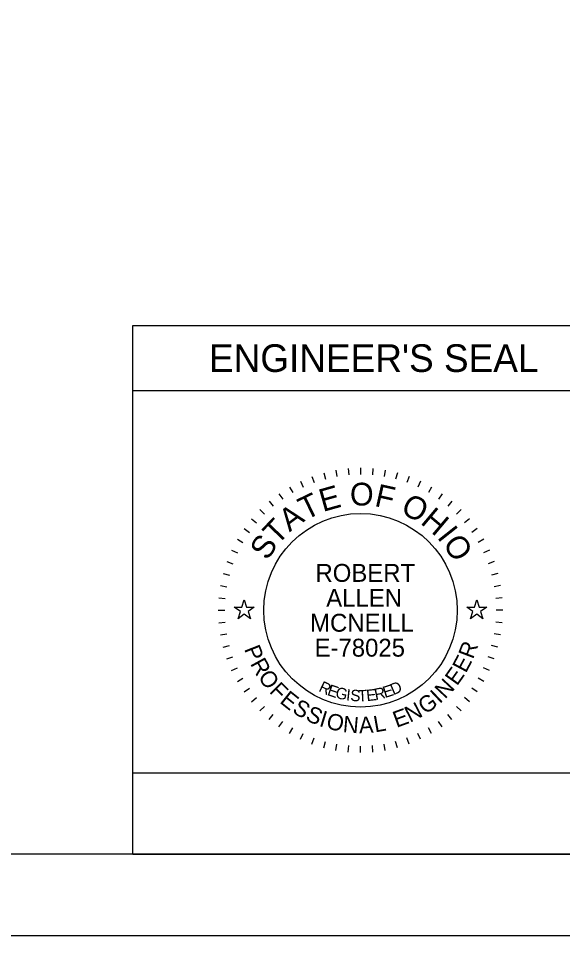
# Model space of a CAD drawing. Extents: x 0 to 34, y 0 to 22.
# Drawn here: x 6.64 to 9.99, y 0 to 5.64 of the extents above; entities that cross this region are included whole.
import ezdxf

# ---------------------------------------------------------------- set-up
doc = ezdxf.new("R2010")
doc.units = 0
for name, color, linetype in [('Default', 7, 'Continuous'), ('SH_Border', 7, 'Continuous'), ('SH_Cut_Line', 7, 'Continuous'), ('SH_Data', 7, 'Continuous')]:
    doc.layers.add(name, color=color, linetype=linetype)

msp = doc.modelspace()

# ---------------------------------------------------------------- linework, layer by layer
at = {"layer": 'Default'}
for points in [[(7.9736, 2.02), (8.0205, 2.02), (8.035, 2.0645), (8.0495, 2.02), (8.0964, 2.02), (8.0585, 1.9924), (8.073, 1.9478), (8.035, 1.9754), (7.997, 1.9478), (8.0115, 1.9924)], [(9.4036, 2.02), (9.4505, 2.02), (9.465, 2.0645), (9.4795, 2.02), (9.5264, 2.02), (9.4885, 1.9924), (9.503, 1.9478), (9.465, 1.9754), (9.427, 1.9478), (9.4415, 1.9924)]]:
    msp.add_lwpolyline(points, close=True, dxfattribs=at)
at = {"layer": 'SH_Border'}
msp.add_lwpolyline([(1.5, 21.5), (33.5, 21.5), (33.5, 0.5), (1.5, 0.5)], close=True, dxfattribs=at)
at = {"layer": 'SH_Cut_Line'}
msp.add_lwpolyline([(0, 0), (34, 0), (34, 22), (0, 22)], close=True, dxfattribs=at)
at = {"layer": 'SH_Data'}
for p, q in [((7.35, 0.5), (7.35, 3.75)), ((7.35, 3.75), (10.15, 3.75)), ((7.35, 3.35), (10.15, 3.35)), ((8.4507, 2.8222), (8.4644, 2.7846)), ((8.5235, 2.8452), (8.5339, 2.8065)), ((8.5981, 2.8617), (8.605, 2.8223)), ((8.6737, 2.8717), (8.6772, 2.8318)), ((8.75, 2.875), (8.75, 2.835)), ((8.8263, 2.8717), (8.8228, 2.8318)), ((8.9019, 2.8617), (8.895, 2.8223)), ((8.9765, 2.8452), (8.9661, 2.8065)), ((9.0493, 2.8222), (9.0356, 2.7846)), ((8.3802, 2.793), (8.3971, 2.7568)), ((9.1198, 2.793), (9.1029, 2.7568)), ((8.2481, 2.7168), (8.2711, 2.684)), ((8.3125, 2.7578), (8.3325, 2.7231)), ((9.1875, 2.7578), (9.1675, 2.7231)), ((9.2519, 2.7168), (9.2289, 2.684)), ((8.1876, 2.6703), (8.2133, 2.6396)), ((9.3124, 2.6703), (9.2867, 2.6396)), ((8.1313, 2.6187), (8.1596, 2.5904)), ((9.3687, 2.6187), (9.3404, 2.5904)), ((8.0797, 2.5624), (8.1104, 2.5367)), ((9.4203, 2.5624), (9.3896, 2.5367)), ((8.0332, 2.5019), (8.066, 2.4789)), ((9.4668, 2.5019), (9.434, 2.4789)), ((7.9922, 2.4375), (8.0269, 2.4175)), ((9.5078, 2.4375), (9.4731, 2.4175)), ((7.957, 2.3698), (7.9932, 2.3529)), ((9.543, 2.3698), (9.5068, 2.3529)), ((7.9278, 2.2993), (7.9654, 2.2856)), ((9.5722, 2.2993), (9.5346, 2.2856)), ((7.9048, 2.2265), (7.9435, 2.2161)), ((9.5952, 2.2265), (9.5565, 2.2161)), ((7.8883, 2.1519), (7.9277, 2.145)), ((9.6117, 2.1519), (9.5723, 2.145)), ((7.8783, 2.0763), (7.9182, 2.0728)), ((9.6217, 2.0763), (9.5818, 2.0728)), ((7.875, 2), (7.915, 2)), ((9.625, 2), (9.585, 2)), ((7.8783, 1.9237), (7.9182, 1.9272)), ((9.6217, 1.9237), (9.5818, 1.9272)), ((7.8883, 1.8481), (7.9277, 1.855)), ((9.6117, 1.8481), (9.5723, 1.855)), ((7.9048, 1.7735), (7.9435, 1.7839)), ((9.5952, 1.7735), (9.5565, 1.7839)), ((7.9278, 1.7007), (7.9654, 1.7144)), ((9.5722, 1.7007), (9.5346, 1.7144)), ((7.957, 1.6302), (7.9932, 1.6471)), ((9.543, 1.6302), (9.5068, 1.6471)), ((7.9922, 1.5625), (8.0269, 1.5825)), ((9.5078, 1.5625), (9.4731, 1.5825)), ((8.0332, 1.4981), (8.066, 1.5211)), ((9.4668, 1.4981), (9.434, 1.5211)), ((8.0797, 1.4376), (8.1104, 1.4633)), ((9.4203, 1.4376), (9.3896, 1.4633)), ((8.1313, 1.3813), (8.1596, 1.4096)), ((8.1876, 1.3297), (8.2133, 1.3604)), ((9.3124, 1.3297), (9.2867, 1.3604)), ((9.3687, 1.3813), (9.3404, 1.4096)), ((8.2481, 1.2832), (8.2711, 1.316)), ((9.2519, 1.2832), (9.2289, 1.316)), ((8.3125, 1.2422), (8.3325, 1.2769)), ((8.3802, 1.207), (8.3971, 1.2432)), ((9.1198, 1.207), (9.1029, 1.2432)), ((9.1875, 1.2422), (9.1675, 1.2769)), ((8.4507, 1.1778), (8.4644, 1.2154)), ((8.5235, 1.1548), (8.5339, 1.1935)), ((8.9765, 1.1548), (8.9661, 1.1935)), ((9.0493, 1.1778), (9.0356, 1.2154)), ((8.5981, 1.1383), (8.605, 1.1777)), ((8.6737, 1.1283), (8.6772, 1.1682)), ((8.75, 1.125), (8.75, 1.165)), ((8.8263, 1.1283), (8.8228, 1.1682)), ((8.9019, 1.1383), (8.895, 1.1777)), ((7.35, 0.5), (10.15, 0.5))]:
    msp.add_line(p, q, dxfattribs=at)
msp.add_lwpolyline([(7.35, 0.5), (7.35, 1), (10.15, 1), (10.15, 0.5)], close=True, dxfattribs=at)
msp.add_circle((8.75, 2), 0.595, dxfattribs=at)

# ---------------------------------------------------------------- texts
for s, height, p in [("ENGINEER'S SEAL", 0.17, (7.8176, 3.465)), ('ROBERT', 0.11, (8.4728, 2.1749)), ('ALLEN', 0.11, (8.5389, 2.0216)), ('MCNEILL', 0.11, (8.4398, 1.8684)), ('E-78025', 0.11, (8.4673, 1.7151))]:
    msp.add_text(s, height=height, dxfattribs=at).set_placement(p)
for s, height, rotation, p in [('E', 0.14, 15.7571, (8.5184, 2.6038)), ('O', 0.14, 359.7812, (8.6847, 2.6443)), ('F', 0.14, 347.4362, (8.8311, 2.6417)), ('T', 0.14, 25.7167, (8.4116, 2.5518)), ('O', 0.14, 332.2586, (8.9898, 2.6015)), ('A', 0.14, 36.4747, (8.3134, 2.4781)), ('H', 0.14, 319.9136, (9.1132, 2.5361)), ('T', 0.14, 46.4344, (8.2383, 2.3964)), ('I', 0.14, 308.367, (9.2165, 2.4483)), ('S', 0.14, 57.1924, (8.1781, 2.3014)), ('O', 0.14, 303.1491, (9.2521, 2.4089)), ('R', 0.1, 69.2322, (9.4419, 1.6954)), ('P', 0.1, 291.494, (8.0323, 1.7621)), ('R', 0.1, 298.7311, (8.069, 1.6717)), ('E', 0.1, 61.9951, (9.3976, 1.6098)), ('E', 0.1, 54.758, (9.3433, 1.5314)), ('O', 0.1, 306.4666, (8.1155, 1.5883)), ('N', 0.1, 47.0224, (9.2702, 1.4508)), ('F', 0.1, 314.7068, (8.1843, 1.4983)), ('R', 0.07, 334.487, (8.4875, 1.5051)), ('E', 0.07, 341.04, (8.5406, 1.4801)), ('G', 0.07, 347.4752, (8.5914, 1.4618)), ('R', 0.07, 11.9184, (8.8425, 1.4474)), ('E', 0.07, 17.6836, (8.8998, 1.4602)), ('D', 0.07, 23.3052, (8.951, 1.477)), ('E', 0.1, 321.4393, (8.2478, 1.4348)), ('I', 0.07, 353.7858, (8.6591, 1.4468)), ('S', 0.07, 356.8926, (8.6858, 1.4429)), ('T', 0.07, 3.0061, (8.7357, 1.4387)), ('E', 0.07, 6.0117, (8.7889, 1.4412)), ('G', 0.1, 35.0469, (9.1481, 1.357)), ('I', 0.1, 43.287, (9.2368, 1.4214)), ('S', 0.1, 328.6764, (8.3243, 1.3752)), ('N', 0.1, 27.3113, (9.0545, 1.3075)), ('S', 0.1, 335.9134, (8.4064, 1.3266)), ('I', 0.1, 343.1505, (8.4906, 1.2897)), ('O', 0.1, 346.8859, (8.5339, 1.2751)), ('E', 0.1, 20.0742, (8.9712, 1.277)), ('N', 0.1, 355.1261, (8.6388, 1.2517)), ('A', 0.1, 2.8617, (8.7423, 1.2437)), ('L', 0.1, 10.0987, (8.8394, 1.249))]:
    msp.add_text(s, height=height, rotation=rotation, dxfattribs=at).set_placement(p)

doc.saveas('drawing.dxf')
